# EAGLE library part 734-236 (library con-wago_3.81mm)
Serie 734, Stiftleiste (für Leiterplatten) Einlötstift gerade 1 x 1 mm / Series 734, Male header (for PCBs) Straight solder pin 1 x 1 mm Polzahl / Pole No.: 6 Rastermaß / Pitch: 3.81 mm Bemessungsspannung / Rated Voltage: 160 V Nennstrom / Nominal Current: 10 A Lötstiftlänge: / Solder Pin Length: 4.5 mm Farbe / Color: orange / orange Stand: 01.01.2012. Die jeweils aktuellen Daten zu diesem Artikel finden Sie in unserem Produktkatalog, den Sie unter www.wago.com einsehen können. As of: 01/01/2012. Please find the newest data for this article in our product catalogue, which can be viewed under www.wago.com.
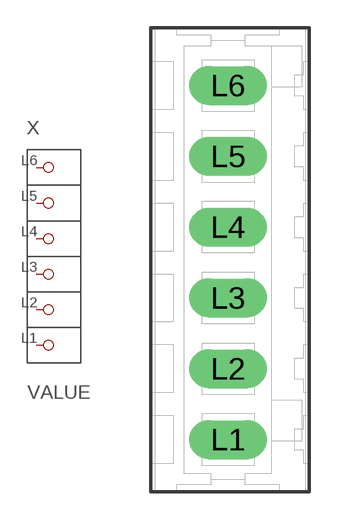
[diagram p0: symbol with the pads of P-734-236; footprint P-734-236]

Designator prefix X

## 734-236  [P-734-236]
L1  P1
L2  P2
L3  P3
L4  P4
L5  P5
L6  P6

## Footprint P-734-236 (pad centres in mm)
drill 1.4 long: L1 -0.1,-9.675; L2 -0.1,-5.865; L3 -0.1,-2.055; L4 -0.1,1.755; L5 -0.1,5.565; L6 -0.1,9.375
